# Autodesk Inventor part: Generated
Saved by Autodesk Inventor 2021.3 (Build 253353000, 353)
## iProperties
Created: 2021-12
Part Number: Generated
Material: Generic
Document SubType Name: Modeling
Designer: Administrator
Density: 1 g/cm^3
Appearance: Default
Title: Generated v1
Author: Administrator
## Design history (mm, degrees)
feature "Body13"
body "Solid1"
